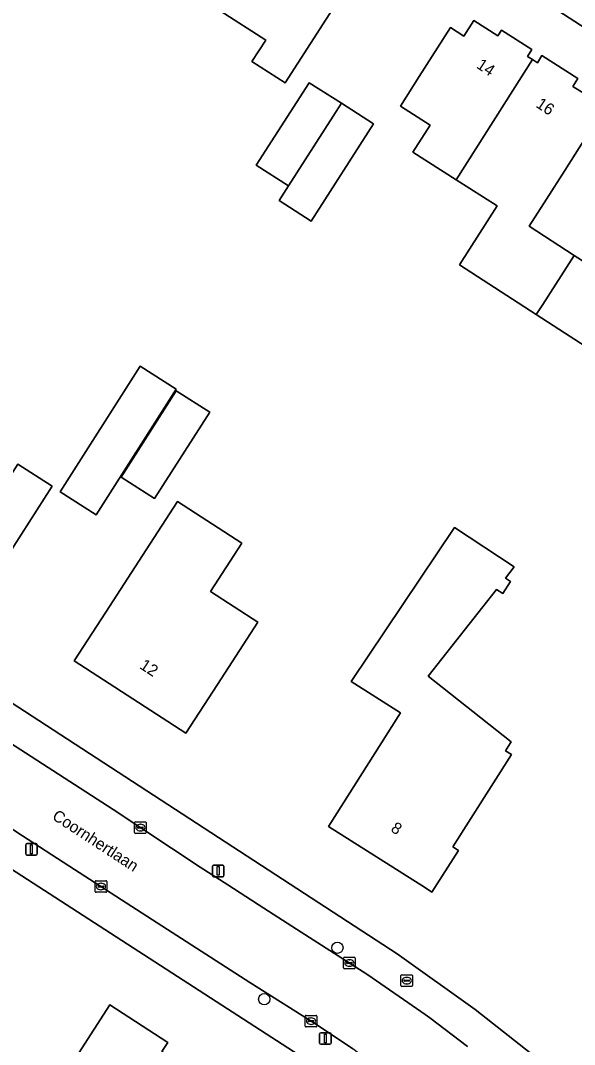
# Model space of a CAD drawing. Extents: x 161139 to 161601, y 381708 to 382245.
# Drawn here: x 161346.4 to 161394.2, y 381929.2 to 382017.4 of the extents above; entities that cross this region are included whole.
import ezdxf

# ---------------------------------------------------------------- set-up
doc = ezdxf.new("R2010")
doc.units = 0
for name, color, linetype in [('IMGEO_Boom', 7, 'Continuous'), ('IMGEO_Brandkraan', 7, 'Continuous'), ('IMGEO_Erf', 7, 'Continuous'), ('IMGEO_Kolk', 7, 'Continuous'), ('IMGEO_Lichtmast', 7, 'Continuous'), ('IMGEO_Openbare_ruimte_label', 7, 'Continuous'), ('IMGEO_Pand', 7, 'Continuous'), ('IMGEO_Pand_nummerreeks', 7, 'Continuous'), ('IMGEO_Rijbaan_lokaal_open', 7, 'Continuous'), ('IMGEO_Voetpad_open', 7, 'Continuous')]:
    doc.layers.add(name, color=color, linetype=linetype)

msp = doc.modelspace()

# ---------------------------------------------------------------- linework, layer by layer
at = {"layer": 'IMGEO_Boom'}
for centre in [(161373.765, 381937.525), (161367.465, 381933.088)]:
    msp.add_circle(centre, 0.489, dxfattribs=at)
at = {"layer": 'IMGEO_Brandkraan'}
for p, q in [((161379.314, 381935.191), (161380.166, 381935.191)), ((161379.239, 381934.265), (161379.239, 381935.117)), ((161379.498, 381934.685), (161379.498, 381934.697)), ((161379.936, 381934.648), (161379.538, 381934.648)), ((161379.541, 381934.734), (161379.939, 381934.734)), ((161379.75, 381934.411), (161379.725, 381934.411)), ((161379.727, 381934.971), (161379.752, 381934.971)), ((161379.982, 381934.697), (161379.982, 381934.685)), ((161380.24, 381935.117), (161380.24, 381934.265)), ((161380.166, 381934.191), (161379.314, 381934.191))]:
    msp.add_line(p, q, dxfattribs=at)
for points in [[(161379.314, 381935.191), (161380.166, 381935.191)], [(161379.239, 381934.265), (161379.239, 381935.117)], [(161380.24, 381935.117), (161380.24, 381934.265)], [(161380.166, 381934.191), (161379.314, 381934.191)]]:
    msp.add_lwpolyline(points, dxfattribs=at)
for centre, radius, start, end in [((161379.316, 381935.115), 0.0765, 91.55205, 178.44795), ((161379.316, 381935.115), 0.0765, 91.55205, 178.44795), ((161380.164, 381935.115), 0.0765, 1.55205, 88.44795), ((161380.164, 381935.115), 0.0765, 1.55205, 88.44795), ((161379.538, 381934.694), 0.0403, 85.87752, 175.75265), ((161379.535, 381934.684), 0.0366, 178.93798, 274.71019), ((161379.939, 381934.691), 0.043, 264.86636, 352.45326), ((161379.943, 381934.696), 0.0386, 1.73085, 96.63898), ((161379.316, 381934.267), 0.0765, 181.55205, 268.44795), ((161379.316, 381934.267), 0.0765, 181.55205, 268.44795), ((161380.164, 381934.267), 0.0765, 271.55205, 358.44795), ((161380.164, 381934.267), 0.0765, 271.55205, 358.44795)]:
    msp.add_arc(centre, radius, start, end, dxfattribs=at)
for centre, major_axis, ratio, start_param, end_param in [((161379.726, 381934.691), (-0.387, 0.002), 0.722429, 4.712389, 7.853982), ((161379.751, 381934.691), (-0.39, 0.002), 0.717154, 1.570796, 4.712389)]:
    msp.add_ellipse(centre, major_axis=major_axis, ratio=ratio, start_param=start_param, end_param=end_param, dxfattribs=at)
at = {"layer": 'IMGEO_Erf'}
for points in [[(161421.048, 382000), (161306.066, 382074.349)], [(161301.893, 382073.339), (161290.838, 382055.877), (161287.538, 382048.363), (161285.187, 382041.077), (161283.628, 382034.817), (161278.294, 382002.287), (161281.877, 382000), (161299.823, 381988.353), (161310.674, 381981.109), (161322.611, 381973.432), (161322.712, 381973.551), (161378.924, 381936.994), (161385.641, 381932.206), (161392.817, 381926.552), (161429.313, 381896.994)], [(161396.68, 381988.351), (161390.905, 381992.091), (161384.298, 381996.37), (161387.531, 382001.458), (161384.011, 382003.694), (161380.269, 382006.071), (161381.751, 382008.404), (161379.19, 382010.031), (161380.819, 382012.595), (161383.5, 382016.815), (161384.673, 382016.07), (161385.525, 382017.411), (161387.592, 382016.097), (161387.902, 382016.585), (161390.522, 382014.92), (161390.145, 382014.327), (161390.576, 382014.054), (161391.004, 382013.782), (161391.396, 382014.399), (161394.499, 382012.428), (161394.066, 382011.748), (161395.777, 382010.661)], [(161396.031, 382008.728), (161393.351, 382004.508), (161391.78, 382002.036), (161390.296, 381999.701), (161394.166, 381997.171), (161398.38, 381994.461)], [(161370.462, 381928.258), (161276.309, 381989.126), (161276.14, 381989.025), (161267.873, 381937.797), (161267.435, 381933.784), (161267.467, 381929.855), (161267.871, 381925.589), (161268.634, 381921.624), (161269.796, 381917.444), (161271.533, 381912.948), (161272.783, 381910.378), (161277.045, 381903.774)]]:
    msp.add_lwpolyline(points, dxfattribs=at)
for points in [[(161359.669, 382020.808), (161358.499, 382018.98), (161355.762, 382020.732), (161357.956, 382024.159), (161360.651, 382028.37), (161361.044, 382028.118), (161363.016, 382031.198), (161365.6, 382029.544), (161366.437, 382030.853), (161370.18, 382028.457), (161373.925, 382026.06), (161373.085, 382024.748), (161375.732, 382023.053), (161373.728, 382019.922), (161374.141, 382019.658), (161371.446, 382015.447), (161369.264, 382012.038), (161366.393, 382013.876), (161367.587, 382015.74), (161363.651, 382018.259)], [(161368.738, 382001.908), (161369.553, 382003.166), (161366.763, 382004.969), (161371.341, 382012.053), (161374.103, 382010.292), (161376.865, 382008.53), (161371.513, 382000.138)], [(161345.229, 381971.099), (161345.094, 381971.185), (161344.863, 381970.822), (161342.904, 381972.07), (161342.662, 381971.691), (161342.021, 381972.099), (161340.338, 381969.467), (161336.1, 381972.176), (161336.689, 381973.098), (161334.659, 381974.396), (161334.413, 381974.038), (161329.982, 381976.855), (161332.06, 381980.096), (161331.431, 381980.495), (161336.33, 381988.176), (161341.044, 381985.169), (161339.024, 381982.002), (161345.419, 381977.923), (161346.226, 381979.188), (161349.184, 381977.301)], [(161352.976, 381974.835), (161349.863, 381976.821), (161356.765, 381987.643), (161359.878, 381985.658)], [(161358.01, 381976.224), (161355.121, 381978.069), (161359.879, 381985.518), (161362.768, 381983.673)], [(161359.985, 381975.96), (161365.513, 381972.374), (161362.821, 381968.223), (161366.916, 381965.576), (161363.429, 381960.199), (161360.708, 381956.003), (161351.088, 381962.243), (161353.809, 381966.438), (161357.287, 381971.8)], [(161379.203, 381957.768), (161374.963, 381960.456), (161383.849, 381973.742), (161389.01, 381970.341), (161388.242, 381969.367), (161388.689, 381969.074), (161388.021, 381968.053), (161387.483, 381968.405), (161381.588, 381960.931), (161388.738, 381955.254), (161388.686, 381955.172), (161388.261, 381954.502), (161388.772, 381954.178), (161383.721, 381946.207), (161384.189, 381945.91), (161381.912, 381942.316), (161381.345, 381942.675), (161372.992, 381947.969)], [(161351.442, 381928.397), (161354.162, 381932.591), (161359.145, 381929.359), (161358.634, 381928.571), (161359.346, 381928.109), (161365.323, 381924.232), (161359.827, 381915.759), (161356.981, 381917.605), (161353.123, 381911.657), (161350.154, 381913.584), (161353.883, 381919.687), (161350.705, 381921.748), (161349.464, 381919.835), (161346.947, 381921.467)]]:
    msp.add_lwpolyline(points, close=True, dxfattribs=at)
at = {"layer": 'IMGEO_Kolk'}
for p, q in [((161356.285, 381947.451), (161356.285, 381948.303)), ((161356.36, 381948.377), (161357.212, 381948.377)), ((161356.544, 381947.871), (161356.544, 381947.883)), ((161356.982, 381947.834), (161356.584, 381947.834)), ((161356.587, 381947.92), (161356.985, 381947.92)), ((161356.796, 381947.597), (161356.771, 381947.597)), ((161356.773, 381948.157), (161356.798, 381948.157)), ((161357.028, 381947.883), (161357.028, 381947.871)), ((161357.286, 381948.303), (161357.286, 381947.451)), ((161357.212, 381947.377), (161356.36, 381947.377)), ((161352.887, 381942.372), (161352.887, 381943.224)), ((161352.962, 381943.298), (161353.814, 381943.298)), ((161353.888, 381943.224), (161353.888, 381942.372)), ((161353.814, 381942.298), (161352.962, 381942.298)), ((161353.146, 381942.792), (161353.146, 381942.804)), ((161353.584, 381942.755), (161353.186, 381942.755)), ((161353.189, 381942.841), (161353.587, 381942.841)), ((161353.398, 381942.518), (161353.373, 381942.518)), ((161353.375, 381943.078), (161353.4, 381943.078)), ((161353.63, 381942.804), (161353.63, 381942.792)), ((161374.295, 381935.778), (161374.295, 381936.63)), ((161374.37, 381936.704), (161375.222, 381936.704)), ((161374.554, 381936.198), (161374.554, 381936.21)), ((161374.992, 381936.161), (161374.594, 381936.161)), ((161374.597, 381936.247), (161374.995, 381936.247)), ((161374.783, 381936.484), (161374.808, 381936.484)), ((161375.038, 381936.21), (161375.038, 381936.198)), ((161375.296, 381936.63), (161375.296, 381935.778)), ((161375.222, 381935.704), (161374.37, 381935.704)), ((161374.806, 381935.924), (161374.781, 381935.924)), ((161371.07, 381931.696), (161371.922, 381931.696)), ((161370.995, 381930.77), (161370.995, 381931.622)), ((161371.254, 381931.19), (161371.254, 381931.202)), ((161371.692, 381931.153), (161371.294, 381931.153)), ((161371.297, 381931.239), (161371.695, 381931.239)), ((161371.506, 381930.916), (161371.481, 381930.916)), ((161371.483, 381931.476), (161371.508, 381931.476)), ((161371.738, 381931.202), (161371.738, 381931.19)), ((161371.996, 381931.622), (161371.996, 381930.77)), ((161371.922, 381930.696), (161371.07, 381930.696))]:
    msp.add_line(p, q, dxfattribs=at)
for points in [[(161356.285, 381947.451), (161356.285, 381948.303)], [(161356.36, 381948.377), (161357.212, 381948.377)], [(161357.286, 381948.303), (161357.286, 381947.451)], [(161357.212, 381947.377), (161356.36, 381947.377)], [(161352.887, 381942.372), (161352.887, 381943.224)], [(161352.962, 381943.298), (161353.814, 381943.298)], [(161353.888, 381943.224), (161353.888, 381942.372)], [(161353.814, 381942.298), (161352.962, 381942.298)], [(161374.295, 381935.778), (161374.295, 381936.63)], [(161374.37, 381936.704), (161375.222, 381936.704)], [(161375.296, 381936.63), (161375.296, 381935.778)], [(161375.222, 381935.704), (161374.37, 381935.704)], [(161371.07, 381931.696), (161371.922, 381931.696)], [(161370.995, 381930.77), (161370.995, 381931.622)], [(161371.996, 381931.622), (161371.996, 381930.77)], [(161371.922, 381930.696), (161371.07, 381930.696)]]:
    msp.add_lwpolyline(points, dxfattribs=at)
for centre, radius, start, end in [((161356.362, 381948.301), 0.0765, 91.55205, 178.44795), ((161356.362, 381948.301), 0.0765, 91.55205, 178.44795), ((161356.584, 381947.88), 0.0403, 85.87752, 175.75265), ((161356.581, 381947.87), 0.0366, 178.93798, 274.71019), ((161356.985, 381947.877), 0.043, 264.86636, 352.45326), ((161356.989, 381947.882), 0.0386, 1.73085, 96.63898), ((161357.21, 381948.301), 0.0765, 1.55205, 88.44795), ((161357.21, 381948.301), 0.0765, 1.55205, 88.44795), ((161356.362, 381947.453), 0.0765, 181.55205, 268.44795), ((161356.362, 381947.453), 0.0765, 181.55205, 268.44795), ((161357.21, 381947.453), 0.0765, 271.55205, 358.44795), ((161357.21, 381947.453), 0.0765, 271.55205, 358.44795), ((161352.964, 381943.222), 0.0765, 91.55205, 178.44795), ((161352.964, 381943.222), 0.0765, 91.55205, 178.44795), ((161353.812, 381943.222), 0.0765, 1.55205, 88.44795), ((161353.812, 381943.222), 0.0765, 1.55205, 88.44795), ((161352.964, 381942.374), 0.0765, 181.55205, 268.44795), ((161352.964, 381942.374), 0.0765, 181.55205, 268.44795), ((161353.186, 381942.801), 0.0403, 85.87752, 175.75265), ((161353.183, 381942.791), 0.0366, 178.93798, 274.71019), ((161353.587, 381942.798), 0.043, 264.86636, 352.45326), ((161353.591, 381942.803), 0.0386, 1.73085, 96.63898), ((161353.812, 381942.374), 0.0765, 271.55205, 358.44795), ((161353.812, 381942.374), 0.0765, 271.55205, 358.44795), ((161374.372, 381936.628), 0.0765, 91.55205, 178.44795), ((161374.372, 381936.628), 0.0765, 91.55205, 178.44795), ((161374.594, 381936.207), 0.0403, 85.87752, 175.75265), ((161374.591, 381936.197), 0.0366, 178.93798, 274.71019), ((161374.995, 381936.204), 0.043, 264.86636, 352.45326), ((161374.999, 381936.209), 0.0386, 1.73085, 96.63898), ((161375.22, 381936.628), 0.0765, 1.55205, 88.44795), ((161375.22, 381936.628), 0.0765, 1.55205, 88.44795), ((161374.372, 381935.78), 0.0765, 181.55205, 268.44795), ((161374.372, 381935.78), 0.0765, 181.55205, 268.44795), ((161375.22, 381935.78), 0.0765, 271.55205, 358.44795), ((161375.22, 381935.78), 0.0765, 271.55205, 358.44795), ((161371.072, 381931.62), 0.0765, 91.55205, 178.44795), ((161371.072, 381931.62), 0.0765, 91.55205, 178.44795), ((161371.92, 381931.62), 0.0765, 1.55205, 88.44795), ((161371.92, 381931.62), 0.0765, 1.55205, 88.44795), ((161371.072, 381930.772), 0.0765, 181.55205, 268.44795), ((161371.072, 381930.772), 0.0765, 181.55205, 268.44795), ((161371.294, 381931.199), 0.0403, 85.87752, 175.75265), ((161371.291, 381931.189), 0.0366, 178.93798, 274.71019), ((161371.695, 381931.196), 0.043, 264.86636, 352.45326), ((161371.699, 381931.201), 0.0386, 1.73085, 96.63898), ((161371.92, 381930.772), 0.0765, 271.55205, 358.44795), ((161371.92, 381930.772), 0.0765, 271.55205, 358.44795)]:
    msp.add_arc(centre, radius, start, end, dxfattribs=at)
for centre, major_axis, ratio, start_param, end_param in [((161356.772, 381947.877), (-0.387, 0.002), 0.722429, 4.712389, 7.853982), ((161356.797, 381947.877), (-0.39, 0.002), 0.717154, 1.570796, 4.712389), ((161353.374, 381942.798), (-0.387, 0.002), 0.722429, 4.712389, 7.853982), ((161353.399, 381942.798), (-0.39, 0.002), 0.717154, 1.570796, 4.712389), ((161374.782, 381936.204), (-0.387, 0.002), 0.722429, 4.712389, 7.853982), ((161374.807, 381936.204), (-0.39, 0.002), 0.717154, 1.570796, 4.712389), ((161371.482, 381931.196), (-0.387, 0.002), 0.722429, 4.712389, 7.853982), ((161371.507, 381931.196), (-0.39, 0.002), 0.717154, 1.570796, 4.712389)]:
    msp.add_ellipse(centre, major_axis=major_axis, ratio=ratio, start_param=start_param, end_param=end_param, dxfattribs=at)
at = {"layer": 'IMGEO_Lichtmast'}
for p, q in [((161346.897, 381945.6), (161346.897, 381946.4)), ((161346.897, 381946.4), (161346.897, 381945.6)), ((161346.997, 381946.5), (161347.787, 381946.5)), ((161347.787, 381946.5), (161346.997, 381946.5)), ((161347.887, 381946.4), (161347.887, 381945.6)), ((161347.887, 381945.6), (161347.887, 381946.4)), ((161347.787, 381945.5), (161346.997, 381945.5)), ((161346.997, 381945.5), (161347.787, 381945.5)), ((161362.995, 381943.742), (161362.995, 381944.542)), ((161362.995, 381944.542), (161362.995, 381943.742)), ((161363.095, 381944.642), (161363.885, 381944.642)), ((161363.885, 381944.642), (161363.095, 381944.642)), ((161363.985, 381944.542), (161363.985, 381943.742)), ((161363.985, 381943.742), (161363.985, 381944.542)), ((161363.885, 381943.642), (161363.095, 381943.642)), ((161363.095, 381943.642), (161363.885, 381943.642)), ((161372.225, 381929.301), (161372.225, 381930.101)), ((161372.225, 381930.101), (161372.225, 381929.301)), ((161372.325, 381930.201), (161373.115, 381930.201)), ((161373.115, 381930.201), (161372.325, 381930.201)), ((161373.215, 381930.101), (161373.215, 381929.301)), ((161373.215, 381929.301), (161373.215, 381930.101)), ((161373.115, 381929.201), (161372.325, 381929.201)), ((161372.325, 381929.201), (161373.115, 381929.201))]:
    msp.add_line(p, q, dxfattribs=at)
for points in [[(161347.317, 381946.375), (161347.467, 381946.375), (161347.467, 381945.625), (161347.317, 381945.625), (161347.317, 381946.375)], [(161363.415, 381944.517), (161363.565, 381944.517), (161363.565, 381943.767), (161363.415, 381943.767), (161363.415, 381944.517)], [(161372.645, 381930.076), (161372.795, 381930.076), (161372.795, 381929.326), (161372.645, 381929.326), (161372.645, 381930.076)]]:
    msp.add_lwpolyline(points, dxfattribs=at)
for centre, start, end in [((161346.997, 381946.4), 90, 180), ((161346.997, 381946.4), 90, 180), ((161347.787, 381946.4), 0, 90), ((161347.787, 381946.4), 360, 90), ((161346.997, 381945.6), 180, 270), ((161346.997, 381945.6), 180, 270), ((161347.787, 381945.6), 270, 0), ((161347.787, 381945.6), 270, 0), ((161363.095, 381944.542), 90, 180), ((161363.095, 381944.542), 90, 180), ((161363.885, 381944.542), 0, 90), ((161363.885, 381944.542), 360, 90), ((161363.095, 381943.742), 180, 270), ((161363.095, 381943.742), 180, 270), ((161363.885, 381943.742), 270, 0), ((161363.885, 381943.742), 270, 0), ((161372.325, 381930.101), 90, 180), ((161372.325, 381930.101), 90, 180), ((161373.115, 381930.101), 0, 90), ((161373.115, 381930.101), 360, 90), ((161372.325, 381929.301), 180, 270), ((161372.325, 381929.301), 180, 270), ((161373.115, 381929.301), 270, 0), ((161373.115, 381929.301), 270, 0)]:
    msp.add_arc(centre, 0.1, start, end, dxfattribs=at)
at = {"layer": 'IMGEO_Pand'}
for points in [[(161370.18, 382028.457), (161363.651, 382018.259), (161367.587, 382015.74), (161366.393, 382013.876), (161369.264, 382012.038), (161371.446, 382015.447), (161374.141, 382019.658), (161373.728, 382019.922), (161375.732, 382023.053), (161373.085, 382024.748), (161373.925, 382026.06)], [(161384.011, 382003.694), (161390.576, 382014.054), (161390.145, 382014.327), (161390.522, 382014.92), (161387.902, 382016.585), (161387.592, 382016.097), (161385.525, 382017.411), (161384.673, 382016.07), (161383.5, 382016.815), (161380.819, 382012.595), (161379.19, 382010.031), (161381.751, 382008.404), (161380.269, 382006.071)], [(161396.031, 382008.728), (161394.975, 382009.398), (161395.777, 382010.661), (161394.066, 382011.748), (161394.499, 382012.428), (161391.396, 382014.399), (161391.004, 382013.782), (161390.576, 382014.054), (161384.011, 382003.694), (161387.531, 382001.458), (161384.298, 381996.37), (161390.905, 381992.091), (161391.465, 381992.964), (161394.166, 381997.171), (161390.296, 381999.701), (161391.78, 382002.036), (161393.351, 382004.508)], [(161374.103, 382010.292), (161371.341, 382012.053), (161366.763, 382004.969), (161369.553, 382003.166)], [(161376.865, 382008.53), (161374.103, 382010.292), (161369.553, 382003.166), (161368.738, 382001.908), (161371.513, 382000.138)], [(161411.569, 382000.234), (161404.87, 382004.554), (161402.163, 382000.351), (161401.942, 382000), (161398.38, 381994.461), (161394.166, 381997.171), (161391.465, 381992.964), (161390.905, 381992.091), (161396.68, 381988.351), (161398.998, 381988.216), (161399.736, 381989.358), (161400.63, 381990.74), (161400.966, 381990.522), (161401.266, 381990.985), (161404.327, 381989.003), (161411.418, 382000)], [(161349.184, 381977.301), (161346.226, 381979.188), (161345.419, 381977.923), (161339.024, 381982.002), (161341.044, 381985.169), (161336.33, 381988.176), (161331.431, 381980.495), (161332.06, 381980.096), (161329.982, 381976.855), (161334.413, 381974.038), (161334.659, 381974.396), (161336.689, 381973.098), (161336.1, 381972.176), (161340.338, 381969.467), (161342.021, 381972.099), (161342.662, 381971.691), (161342.904, 381972.07), (161344.863, 381970.822), (161345.094, 381971.185), (161345.229, 381971.099)], [(161349.863, 381976.821), (161352.976, 381974.835), (161359.878, 381985.658), (161356.765, 381987.643)], [(161358.01, 381976.224), (161362.768, 381983.673), (161359.879, 381985.518), (161355.121, 381978.069)], [(161366.916, 381965.576), (161362.821, 381968.223), (161365.513, 381972.374), (161359.985, 381975.96), (161357.287, 381971.8), (161353.809, 381966.438), (161351.088, 381962.243), (161360.708, 381956.003), (161363.429, 381960.199)], [(161388.772, 381954.178), (161388.261, 381954.502), (161388.686, 381955.172), (161388.738, 381955.254), (161381.588, 381960.931), (161387.483, 381968.405), (161388.021, 381968.053), (161388.689, 381969.074), (161388.242, 381969.367), (161389.01, 381970.341), (161383.849, 381973.742), (161374.963, 381960.456), (161379.203, 381957.768), (161372.992, 381947.969), (161381.345, 381942.675), (161381.912, 381942.316), (161384.189, 381945.91), (161383.721, 381946.207)], [(161353.883, 381919.687), (161359.346, 381928.109), (161358.634, 381928.571), (161359.145, 381929.359), (161354.162, 381932.591), (161351.442, 381928.397), (161346.947, 381921.467), (161349.464, 381919.835), (161350.705, 381921.748)]]:
    msp.add_lwpolyline(points, close=True, dxfattribs=at)
at = {"layer": 'IMGEO_Rijbaan_lokaal_open'}
for points in [[(161354.44, 381949.434), (161345.5, 381955.194), (161345.132, 381955.433), (161341.968, 381957.49), (161334.965, 381962.043), (161325.373, 381968.263), (161318.237, 381972.89), (161316.637, 381973.927), (161310.106, 381978.294), (161303.837, 381982.304), (161300.012, 381984.75), (161296.327, 381987.12), (161278.737, 381998.431)], [(161278.323, 381991.478), (161299.753, 381977.533), (161307.482, 381972.536), (161311.114, 381970.18), (161315.062, 381967.62), (161315.173, 381967.548), (161318.89, 381965.138), (161327.462, 381959.489), (161330.866, 381957.332), (161337.714, 381952.958), (161346.638, 381947.161), (161350.625, 381944.584), (161357.825, 381939.931), (161366.222, 381934.52), (161372.037, 381930.857), (161375.083, 381928.811)], [(161384.971, 381929.006), (161381.728, 381931.469), (161381.315, 381931.756), (161376.383, 381935.18), (161370.251, 381939.135), (161367.432, 381940.939), (161364.318, 381942.933), (161361.946, 381944.451), (161354.44, 381949.434)]]:
    msp.add_lwpolyline(points, dxfattribs=at)
at = {"layer": 'IMGEO_Voetpad_open'}
for points in [[(161306.066, 382074.349), (161421.048, 382000), (161474.804, 381965.241), (161478.068, 381963.057), (161478.909, 381962.515)], [(161392.817, 381926.552), (161385.641, 381932.206), (161378.924, 381936.994), (161322.712, 381973.551), (161322.611, 381973.432), (161310.674, 381981.109), (161299.823, 381988.353), (161281.877, 382000)], [(161327.462, 381959.489), (161318.89, 381965.138), (161315.173, 381967.548), (161315.062, 381967.62), (161311.114, 381970.18), (161307.482, 381972.536), (161299.753, 381977.533), (161278.323, 381991.478), (161276.309, 381989.126), (161370.462, 381928.258), (161376.195, 381924.445)], [(161296.327, 381987.12), (161300.012, 381984.75), (161303.837, 381982.304), (161310.106, 381978.294), (161316.637, 381973.927), (161318.237, 381972.89), (161325.373, 381968.263), (161334.965, 381962.043), (161341.968, 381957.49), (161345.132, 381955.433), (161345.5, 381955.194), (161354.44, 381949.434), (161361.946, 381944.451), (161364.318, 381942.933), (161367.432, 381940.939), (161370.251, 381939.135), (161376.383, 381935.18), (161381.315, 381931.756), (161381.728, 381931.469), (161384.971, 381929.006)], [(161375.58, 381928.429), (161375.083, 381928.811), (161372.037, 381930.857), (161366.222, 381934.52), (161357.825, 381939.931), (161350.625, 381944.584), (161346.638, 381947.161), (161337.714, 381952.958), (161330.866, 381957.332), (161327.462, 381959.489)]]:
    msp.add_lwpolyline(points, dxfattribs=at)

# ---------------------------------------------------------------- texts
at = {"layer": 'IMGEO_Openbare_ruimte_label'}
msp.add_text('Coornhertlaan', height=1, rotation=326.91369, dxfattribs=at).set_placement((161349.104, 381948.652))
at = {"layer": 'IMGEO_Pand_nummerreeks'}
for s, rotation, p in [('14', 326.63877, (161385.67, 382013.388)), ('16', 326.63667, (161390.796, 382010.013)), ('12', 327.03201, (161356.65, 381961.639)), ('8', 327.63361, (161378.289, 381947.595))]:
    msp.add_text(s, height=1, rotation=rotation, dxfattribs=at).set_placement(p)

doc.saveas('drawing.dxf')
